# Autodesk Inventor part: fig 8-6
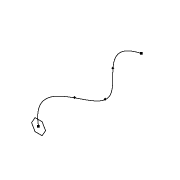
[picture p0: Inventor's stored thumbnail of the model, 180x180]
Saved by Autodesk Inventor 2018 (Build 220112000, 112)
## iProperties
Created: 2006-01
Part Number: fig 8-6
Document SubType Name: Modeling
Designer: CADCIM
Density: 1 g/cm^3
Material: Generic
Appearance: Default
Author: CADCIM
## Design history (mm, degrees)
sketch "Sketch1"
  geometry: 5 further points
  constraints: 5 other
sketch "Sketch2"
  geometry: L1 (-4.728, 0)-(-2.364, 4.094); L2 (-2.364, 4.094)-(2.364, 4.094); L3 (2.364, 4.094)-(4.728, 0); L4 (4.728, 0)-(2.364, -4.094); L5 (2.364, -4.094)-(-2.364, -4.094); L6 (-2.364, -4.094)-(-4.728, 0); 1 further point
  constraints: 12 end point, 13 other
body "Solid1"
